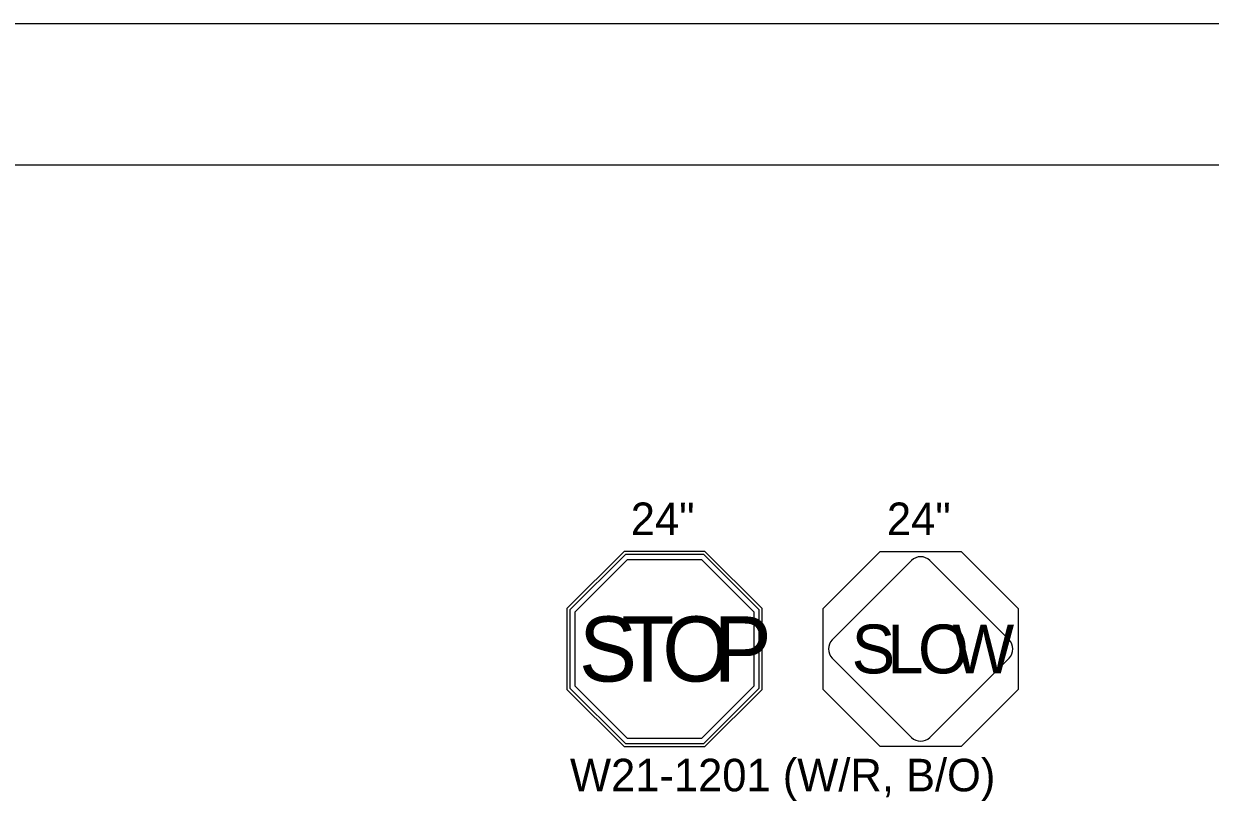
# Model space of a CAD drawing. Extents: x 99998.9 to 100095.7, y 99995 to 100010.7.
# Drawn here: x 100009.772 to 100012.398, y 100008.958 to 100010.687 of the extents above; entities that cross this region are included whole.
import ezdxf

# ---------------------------------------------------------------- set-up
doc = ezdxf.new("R2010")
doc.units = 0
for name, color, linetype in [('SH_GI_PlotLimits', 7, 'Continuous'), ('SH_GI_SheetBorder', 7, 'Continuous'), ('TR_SN_ConstructionSigns', 7, 'Continuous')]:
    doc.layers.add(name, color=color, linetype=linetype)

msp = doc.modelspace()

# ---------------------------------------------------------------- linework, layer by layer
at = {"layer": 'SH_GI_PlotLimits'}
msp.add_lwpolyline([(99999.0625, 99999.6875), (100016.0625, 99999.6875), (100016.0625, 100010.6875), (99999.0625, 100010.6875)], close=True, dxfattribs=at)
at = {"layer": 'SH_GI_SheetBorder'}
msp.add_line((100000, 100010.375), (100015.75, 100010.375), dxfattribs=at)
at = {"layer": 'TR_SN_ConstructionSigns'}
for p, q in [((100011.1006, 100009.5201), (100010.9741, 100009.3936)), ((100011.1034, 100009.5134), (100010.9809, 100009.3908)), ((100010.9921, 100009.3861), (100011.1081, 100009.5021)), ((100011.2796, 100009.5201), (100011.1006, 100009.5201)), ((100011.2768, 100009.5134), (100011.1034, 100009.5134)), ((100011.1081, 100009.5021), (100011.2721, 100009.5021)), ((100011.2721, 100009.5021), (100011.3881, 100009.3861)), ((100011.3994, 100009.3908), (100011.2768, 100009.5134)), ((100011.4061, 100009.3936), (100011.2796, 100009.5201)), ((100011.7367, 100009.4997), (100011.5615, 100009.3245)), ((100011.9527, 100009.3245), (100011.7775, 100009.4997)), ((100010.9741, 100009.3936), (100010.9741, 100009.2146)), ((100011.4061, 100009.2146), (100011.4061, 100009.3936)), ((100010.9809, 100009.3908), (100010.9809, 100009.2174)), ((100010.9921, 100009.2221), (100010.9921, 100009.3861)), ((100011.3881, 100009.3861), (100011.3881, 100009.2221)), ((100011.3994, 100009.2174), (100011.3994, 100009.3908)), ((100011.5615, 100009.2837), (100011.7367, 100009.1085)), ((100011.7775, 100009.1085), (100011.9527, 100009.2837)), ((100010.9741, 100009.2146), (100011.1006, 100009.0881)), ((100010.9809, 100009.2174), (100011.1034, 100009.0949)), ((100011.1081, 100009.1061), (100010.9921, 100009.2221)), ((100011.3881, 100009.2221), (100011.2721, 100009.1061)), ((100011.2768, 100009.0949), (100011.3994, 100009.2174)), ((100011.2796, 100009.0881), (100011.4061, 100009.2146)), ((100011.2721, 100009.1061), (100011.1081, 100009.1061)), ((100011.1006, 100009.0881), (100011.2796, 100009.0881)), ((100011.1034, 100009.0949), (100011.2768, 100009.0949))]:
    msp.add_line(p, q, dxfattribs=at)
msp.add_lwpolyline([(100011.9731, 100009.3936), (100011.9731, 100009.2146), (100011.8466, 100009.0881), (100011.6676, 100009.0881), (100011.5411, 100009.2146), (100011.5411, 100009.3936), (100011.6676, 100009.5201), (100011.8466, 100009.5201)], close=True, dxfattribs=at)
for centre, start, end in [((100011.7571, 100009.4794), 45, 135), ((100011.5818, 100009.3041), 135, 225), ((100011.9324, 100009.3041), 315, 45), ((100011.7571, 100009.1288), 225, 315)]:
    msp.add_arc(centre, 0.0288, start, end, dxfattribs=at)

# ---------------------------------------------------------------- texts
for s, height, p in [('24"', 0.072, (100011.1154, 100009.5561)), ('24"', 0.072, (100011.6824, 100009.5561)), ('S', 0.144, (100011.0007, 100009.2321)), ('T', 0.144, (100011.0943, 100009.2321)), ('O', 0.144, (100011.1851, 100009.2321)), ('P', 0.144, (100011.2988, 100009.2321)), ('S', 0.108, (100011.6043, 100009.2501)), ('L', 0.108, (100011.6831, 100009.2501)), ('O', 0.108, (100011.7512, 100009.2501)), ('W', 0.108, (100011.8279, 100009.2501))]:
    msp.add_text(s, height=height, dxfattribs=at).set_placement(p)
msp.add_text('W21-1201 (W/R, B/O)', height=0.072, rotation=360, dxfattribs=at).set_placement((100010.9809, 100008.9891))

doc.saveas('drawing.dxf')
